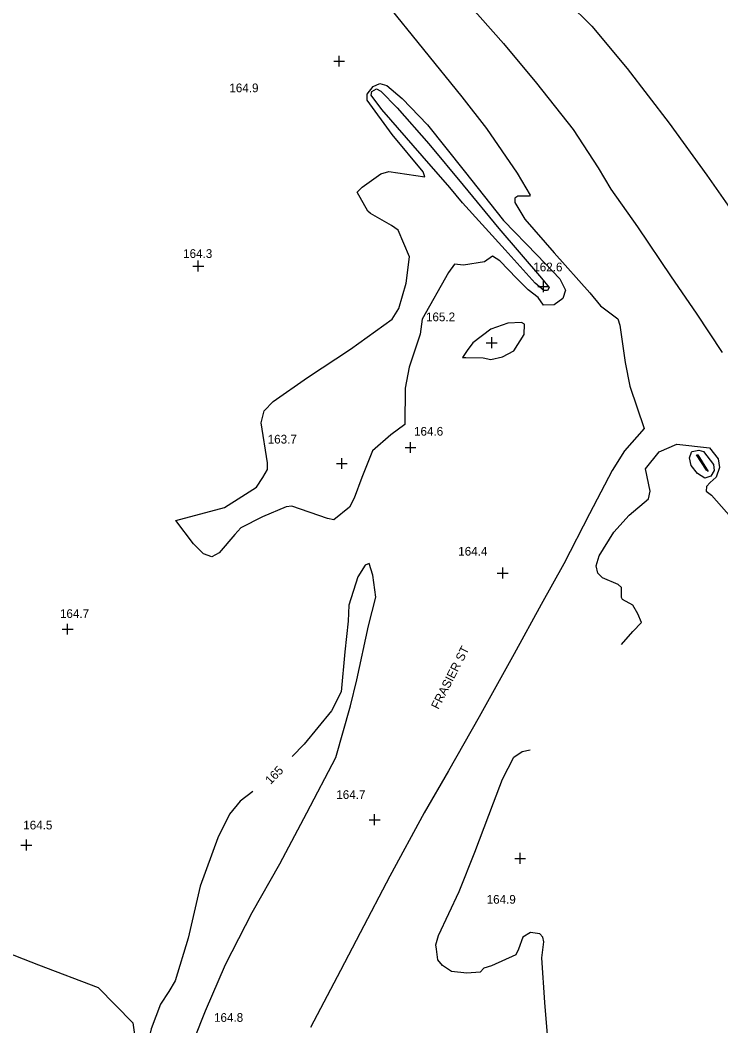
# Model space of a CAD drawing. Extents: x 1475150 to 2003689, y 770235 to 1112803.
# Drawn here: x 1999039.9 to 1999200.7, y 775010.1 to 775241.1 of the extents above; entities that cross this region are included whole.
import ezdxf

# ---------------------------------------------------------------- set-up
doc = ezdxf.new("R2010")
doc.units = 0
for name, color, linetype in [('RD_DTM_Major1', 7, 'Continuous'), ('RD_DTM_Major1_Lbl', 7, 'Continuous'), ('RD_DTM_Minor1', 7, 'Continuous'), ('RD_DTM_Obscure', 7, 'Continuous'), ('RD_DTM_Spot_Elev', 7, 'Continuous'), ('RD_TX_Misc1', 7, 'Continuous')]:
    doc.layers.add(name, color=color, linetype=linetype)

msp = doc.modelspace()

# ---------------------------------------------------------------- linework, layer by layer
at = {"layer": 'RD_DTM_Major1'}
for points in [[(1999123.68, 775245.18), (1999132.48, 775234.35), (1999141.3, 775223.49), (1999146.9, 775216.18), (1999153.95, 775205.9), (1999156.99, 775200.91), (1999156.78, 775200.68), (1999154.12, 775200.68), (1999153.43, 775200.21), (1999153.4, 775199.18), (1999155.72, 775195.39), (1999162.43, 775187.6), (1999170.68, 775178.43), (1999173.09, 775175.47), (1999177.05, 775172.45), (1999177.55, 775170.99), (1999178.78, 775162.45), (1999179.82, 775156.99), (1999183.15, 775147.31), (1999178.63, 775142.17), (1999175.78, 775137.63), (1999170.56, 775127.67), (1999164.68, 775116.23), (1999159.5, 775106.83), (1999153.28, 775095.55), (1999145.25, 775081.09), (1999138.18, 775068.68), (1999132.65, 775058.98), (1999124.71, 775044.44), (1999117.91, 775031.41), (1999113.39, 775022.77), (1999106.54, 775009.68)], [(1999142.17, 775163.61), (1999146.17, 775163.54), (1999147.96, 775163.1), (1999150.59, 775163.73), (1999153.2, 775165.13), (1999155.57, 775168.84), (1999155.62, 775171.21), (1999154.98, 775171.62), (1999151.8, 775171.47), (1999147.96, 775170.06), (1999143.8, 775166.93), (1999142.46, 775165.19), (1999141.39, 775163.6), (1999142.17, 775163.61)], [(1999177.94, 775097.66), (1999177.95, 775097.68), (1999180.54, 775100.65), (1999182.5, 775102.73), (1999181.7, 775104.71), (1999180.54, 775106.74), (1999178.18, 775107.98), (1999177.93, 775108.46), (1999177.93, 775110.77), (1999177.17, 775111.47), (1999173.54, 775112.96), (1999172.46, 775114.04), (1999172.12, 775115.71), (1999172.82, 775118.06), (1999176.17, 775123.5), (1999179.67, 775127.37), (1999184.14, 775131.13), (1999184.48, 775132.91), (1999183.45, 775138.01), (1999186.55, 775141.91), (1999190.66, 775143.72), (1999198.1, 775142.83), (1999200.13, 775140.35), (1999200.46, 775138.35), (1999199.66, 775136.09), (1999198.31, 775134.89), (1999197.47, 775133.95), (1999197.35, 775132.88), (1999198.55, 775131.94), (1999206.08, 775123.46)], [(1999077.52, 775001.22), (1999082.39, 775013.49), (1999087, 775024.14), (1999093.15, 775036.08), (1999099.45, 775047.29), (1999105.71, 775058.99), (1999112.34, 775071.72), (1999115.73, 775083.61), (1999117.15, 775089.52), (1999119.8, 775101.94), (1999121.52, 775108.53), (1999120.86, 775113.62), (1999119.96, 775116.28), (1999119.1, 775115.92), (1999117.39, 775113.21), (1999115.32, 775106.73), (1999115.19, 775103.01), (1999114.42, 775096.01), (1999113.54, 775086.82), (1999111.35, 775082.44), (1999105.06, 775074.76), (1999102.29, 775071.91)], [(1999161.25, 775004.33), (1999160.29, 775015.45), (1999159.62, 775025.71), (1999160.13, 775029.38), (1999159.86, 775030.46), (1999159.14, 775031.19), (1999157.03, 775031.53), (1999155.28, 775030.42), (1999154.29, 775027.72), (1999153.68, 775026.42), (1999148.08, 775023.89), (1999146.3, 775023.29), (1999145.46, 775022.41), (1999142.4, 775022.16), (1999138.93, 775022.59), (1999136.81, 775023.95), (1999135.79, 775025.25), (1999135.44, 775027.72), (1999135.31, 775028.72), (1999135.89, 775030.85), (1999140.67, 775040.94), (1999144.23, 775049.96), (1999148.54, 775061.33), (1999150.6, 775066.76), (1999153.23, 775071.82), (1999155.08, 775073.07), (1999156.97, 775073.51)], [(1999093.32, 775063.9), (1999090.35, 775061.66), (1999087.9, 775058.69), (1999085.26, 775053.24), (1999081.17, 775042.14), (1999078.45, 775030.23), (1999075.47, 775020.42), (1999073.98, 775017.94), (1999072.05, 775015.06), (1999069.94, 775009.38), (1999067.83, 775000.5), (1999067.36, 774999.45)]]:
    msp.add_lwpolyline(points, dxfattribs=at)
at = {"layer": 'RD_DTM_Minor1'}
for points in [[(1999142.5, 775245.14), (1999150.82, 775235.71), (1999158.4, 775226.63), (1999166.8, 775215.99), (1999172.57, 775207.13), (1999175.44, 775202.25), (1999181.6, 775193.6), (1999189.31, 775182.11), (1999195.05, 775173.8), (1999201.02, 775164.71)], [(1999165.5, 775245.22), (1999171.15, 775239.7), (1999179.24, 775229.96), (1999188.86, 775217.38), (1999197.52, 775205.5), (1999203.4, 775197.05)], [(1999120.29, 775196.63), (1999119.68, 775197.18), (1999117.2, 775201.57), (1999118.41, 775202.73), (1999122.64, 775205.75), (1999124.49, 775206.34), (1999132.79, 775205.09), (1999132.37, 775206.22), (1999125.25, 775214.83), (1999119.55, 775222.66), (1999119.56, 775224.06), (1999120.94, 775225.84), (1999122.46, 775226.54), (1999124.08, 775226.04), (1999127.55, 775223.07), (1999133.36, 775217.05), (1999141.79, 775206.44), (1999150.82, 775195.03), (1999158.59, 775187.08), (1999163.73, 775181.64), (1999165.06, 775179.07), (1999164.42, 775177.11), (1999162.5, 775175.67), (1999160, 775175.59), (1999158.79, 775177.38), (1999156.52, 775179.13), (1999153.86, 775181.72), (1999149.97, 775185.79), (1999148.34, 775186.9), (1999146.49, 775185.54), (1999141.63, 775184.77), (1999139.59, 775185.01), (1999138.21, 775183.11), (1999132.15, 775172.4), (1999131.71, 775168.98), (1999129.21, 775161.4), (1999128.28, 775156.51), (1999128.17, 775148.22), (1999124.95, 775145.83), (1999120.79, 775142.18), (1999118.3, 775136.06), (1999116.53, 775131.31), (1999115.49, 775129.22), (1999111.91, 775126.33), (1999110.44, 775126.58), (1999102.21, 775129.46), (1999100.95, 775129.28), (1999095.51, 775126.99), (1999090.56, 775124.43), (1999089.16, 775122.97), (1999085.59, 775118.71), (1999083.86, 775117.83), (1999081.96, 775118.46), (1999079.69, 775120.79), (1999075.63, 775126.14), (1999086.79, 775129.17), (1999090.79, 775131.65), (1999094.16, 775133.78), (1999095.61, 775136.01), (1999096.64, 775137.9), (1999096.62, 775139.38), (1999095.21, 775148.56), (1999095.92, 775151.34), (1999097.95, 775153.47), (1999105.85, 775158.97), (1999115.73, 775165.51), (1999125.24, 775172.4), (1999126.82, 775174.84), (1999128.46, 775180.63), (1999129.22, 775186.68), (1999126.62, 775192.82), (1999125.14, 775193.89), (1999120.29, 775196.63)], [(1999120.44, 775223.81), (1999120.62, 775224.65), (1999121.69, 775225.3), (1999122.68, 775224.75), (1999126.39, 775220.9), (1999133.71, 775212.67), (1999141.58, 775203.15), (1999149.77, 775193.19), (1999159.59, 775181.81), (1999161.34, 775179.65), (1999160.95, 775178.97), (1999160.11, 775178.97), (1999158.12, 775180.65), (1999151.18, 775188.29), (1999141.4, 775199.08), (1999138.53, 775202.62), (1999132.14, 775209.88), (1999122.87, 775220.54), (1999120.44, 775223.81)], [(1999194.14, 775141.97), (1999195.64, 775142.34), (1999196.77, 775142.02), (1999199.08, 775139.04), (1999199.18, 775137.63), (1999198.41, 775136.35), (1999197.03, 775135.88), (1999195.36, 775136.96), (1999193.93, 775138.82), (1999193.51, 775140.52), (1999193.98, 775141.85), (1999194.14, 775141.97)], [(1999195.12, 775141.27), (1999195.46, 775141.21), (1999197.84, 775137.38), (1999197.47, 775137.73), (1999195.12, 775141.27)]]:
    msp.add_lwpolyline(points, dxfattribs=at)
at = {"layer": 'RD_DTM_Obscure'}
msp.add_lwpolyline([(1999027.39, 775030.6), (1999044.06, 775024.08), (1999057.74, 775018.89), (1999065.7, 775010.77), (1999067.49, 774998.6)], dxfattribs=at)
at = {"layer": 'RD_DTM_Spot_Elev'}
for p, q in [((1999113.1, 775230.4), (1999113.1, 775232.9)), ((1999111.85, 775231.65), (1999114.35, 775231.65)), ((1999079.51, 775184.6), (1999082.01, 775184.6)), ((1999080.76, 775183.35), (1999080.76, 775185.85)), ((1999158.75, 775179.86), (1999161.25, 775179.86)), ((1999160, 775178.61), (1999160, 775181.11)), ((1999148.13, 775165.73), (1999148.13, 775168.23)), ((1999146.88, 775166.98), (1999149.38, 775166.98)), ((1999128.23, 775142.93), (1999130.73, 775142.93)), ((1999129.48, 775141.68), (1999129.48, 775144.18)), ((1999113.72, 775138), (1999113.72, 775140.5)), ((1999112.47, 775139.25), (1999114.97, 775139.25)), ((1999150.65, 775112.83), (1999150.65, 775115.33)), ((1999149.4, 775114.08), (1999151.9, 775114.08)), ((1999049.52, 775101.18), (1999052.02, 775101.18)), ((1999050.77, 775099.93), (1999050.77, 775102.43)), ((1999120, 775057.42), (1999122.5, 775057.42)), ((1999121.25, 775056.17), (1999121.25, 775058.67)), ((1999041.3, 775050.36), (1999041.3, 775052.86)), ((1999040.05, 775051.61), (1999042.55, 775051.61)), ((1999154.66, 775047.28), (1999154.66, 775049.78)), ((1999153.41, 775048.53), (1999155.91, 775048.53))]:
    msp.add_line(p, q, dxfattribs=at)

# ---------------------------------------------------------------- texts
at = {"layer": 'RD_DTM_Major1_Lbl'}
msp.add_text('165', height=2, rotation=45.8102, dxfattribs=at).set_placement((1999097.35, 775065.38))
at = {"layer": 'RD_DTM_Spot_Elev'}
for s, p in [('164.9', (1999087.89, 775224.52)), ('164.3', (1999077.28, 775186.46)), ('162.6', (1999157.67, 775183.38)), ('165.2', (1999133.03, 775171.92)), ('164.6', (1999130.29, 775145.64)), ('163.7', (1999096.69, 775143.83)), ('164.4', (1999140.44, 775118.09)), ('164.7', (1999049, 775103.76)), ('164.7', (1999112.44, 775062.19)), ('164.5', (1999040.57, 775055.19)), ('164.9', (1999146.96, 775038.13)), ('164.8', (1999084.37, 775011))]:
    msp.add_text(s, height=2, dxfattribs=at).set_placement(p)
at = {"layer": 'RD_TX_Misc1'}
msp.add_text('FRASIER ST', height=2, rotation=62.9562, dxfattribs=at).set_placement((1999135.88, 775082.63))

doc.saveas('drawing.dxf')
